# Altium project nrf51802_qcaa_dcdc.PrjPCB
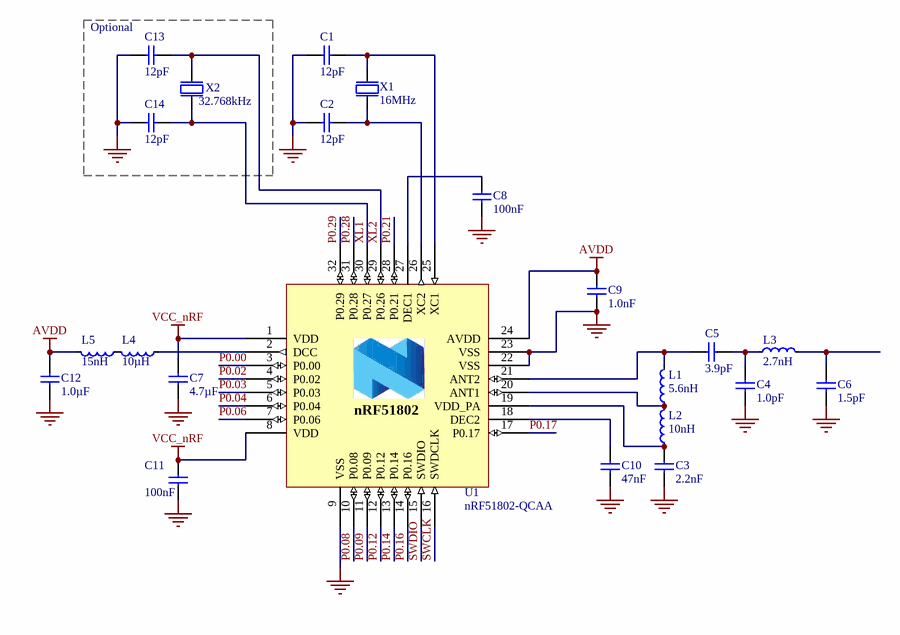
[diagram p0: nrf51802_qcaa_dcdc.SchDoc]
1 sheet, 22 parts. Net scope: global (net labels, ports and power ports of the same name join across sheets).
Board file: nrf51802_qcaa_dcdc.PcbDoc

## Sheet nrf51802_qcaa_dcdc.SchDoc: nRF51802-QCAA Reference Layout (DCDC)
size A4; Revision: 1.0; SheetNumber: 1; SheetTotal: 1; DrawnBy: RUBR; DocumentSize: A4; PCAName: nRF51802-QCAA Reference Layout (DCDC)

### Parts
C1  12pF  [CAPC1005X04L]
C2  12pF  [CAPC1005X04L]
C3  2.2nF  [CAPC1005X04L]
C4  1.0pF  [CAPC1005X04L]
C5  3.9pF  [CAPC1005X04L]
C6  1.5pF  [CAPC1005X04L]
C7  4.7µF  [CAPC1608X06L]
C8  100nF  [CAPC1005X04L]
C9  1.0nF  [CAPC1005X04L]
C10  47nF  [CAPC1005X04L]
C11  100nF  [CAPC1005X04L]
C12  1.0µF  [CAPC1608X06L]
C13  12pF  [CAPC1005X04L]
C14  12pF  [CAPC1005X04L]
L1  5.6nH  [INDC1005X04L]
L2  10nH  [INDC1005X04L]
L3  2.7nH  [INDC1005X04L]
L4  10µH  [INDC1608X06L]
L5  15nH  [INDC1005X04L]
U1  nRF51802-QCAA  [Nordic_QFN50P500X500X90-33N]
X1  16MHz  [BT-XTAL_2520]
X2  32.768kHz  [XTAL_3215]

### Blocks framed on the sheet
Optional: C13 C14 X2

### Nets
AVDD: C9.1 C12.2 L5.2 U1.24(AVDD)
GND: C1.2 C2.2 C3.2 C4.2 C6.2 C7.2 C8.2 C9.2 C10.2 C11.2 C12.1 C13.1 C14.1 U1.9(VSS) U1.22(VSS) U1.23(VSS) U1.33 X1.2(GND) X1.4(GND)
VCC_nRF: C7.1 C11.1 U1.1(VDD) U1.8(VDD)
P0.00: U1.3(P0.00)
P0.02: U1.4(P0.02)
P0.03: U1.5(P0.03)
P0.04: U1.6(P0.04)
P0.06: U1.7(P0.06)
P0.08: U1.10(P0.08)
P0.09: U1.11(P0.09)
P0.12: U1.12(P0.12)
P0.14: U1.13(P0.14)
P0.16: U1.14(P0.16)
P0.17: U1.17(P0.17)
P0.21: U1.28(P0.21)
P0.28: U1.31(P0.28)
P0.29: U1.32(P0.29)
SWCLK: U1.16(SWDCLK)
SWDIO: U1.15(SWDIO)
XL1: C14.2 U1.30(P0.27) X2.2(out)
XL2: C13.2 U1.29(P0.26) X2.1(inp)
NetC1_1: C1.1 U1.25(XC1) X1.1(inp)
NetC2_1: C2.1 U1.26(XC2) X1.3(out)
NetC3_1: C3.1 L2.1 U1.19(VDD_PA)
NetC4_1: C4.1 C5.2 L3.1
NetC5_1: C5.1 L1.2 U1.21(ANT2)
NetC6_1: C6.1 L3.2
NetC8_1: C8.1 U1.27(DEC1)
NetC10_1: C10.1 U1.18(DEC2)
NetL1_1: L1.1 L2.2 U1.20(ANT1)
NetL4_1: L4.1 U1.2(DCC)
NetL4_2: L4.2 L5.1

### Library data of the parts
C1 C2 C13 C14 = C0402-12p: Capacitor, NP0, ±2%; Note: 50V; Artikkelnr Noca: 20029159; Artikkelnr Simpro: N.A.
C3 = C0402-2n2: Capacitor, X7R, ±10%; Note: 50V; Artikkelnr Noca: 20039221; Artikkelnr Simpro: N.A.
C4 = C0402-1.0p: Capacitor, NP0, ±0.1pF; Note: 50V; Artikkelnr Noca: 20029140; Artikkelnr Simpro: N.A.
C5 = C0402-3.9p: Capacitor, NP0, ±0.1pF; Note: 50V; Artikkelnr Noca: N.A.
C6 = C0402-1.5p: Capacitor, NP0, ±0.1pF; Note: 50V; Artikkelnr Noca: 20029139; Artikkelnr Simpro: N.A.
C7 = C0603-4µ7: Capacitor, X5R, ±10%; Note: 6.3V; Artikkelnr Noca: 20069060; Artikkelnr Simpro: N.A.
C8 C11 = C0402-100n: Capacitor, X7R, ±10%; Note: 16V; Artikkelnr Noca: 20039200; Artikkelnr Simpro: N.A.
C9 = C0402-1n0: Capacitor, X7R, ±10%; Note: 50V; Artikkelnr Noca: 20039223; Artikkelnr Simpro: N.A.
C10 = C0402-47n: Capacitor, X7R, ±10%; Note: Chip Cap 10%; Artikkelnr Noca: 20039389; Artikkelnr Simpro: N.A.
C12 = C0603-1µ0: Capacitor, X7R, ±10%; Note: 16V; Artikkelnr Noca: 20039335; Artikkelnr Simpro: N.A.
L1 = L0402-5n6: High frequency chip inductor ±5%; Manufacturer: Murata; Manufacturer Part Number: LQP15MN5N6B02D; Artikkelnr Noca: 33029161; Artikkelnr Simpro: N.A.
L2 = L0402-10n: High frequency chip inductor ±5%; Manufacturer: Murata; Manufacturer Part Number: LQP15MN10NG02D; Artikkelnr Noca: 33029425; Artikkelnr Simpro: N.A.
L3 = L0402-2n7: High frequency chip inductor ±5%; Manufacturer: Murata; Manufacturer Part Number: LQP15MN2N7B02D; Artikkelnr Noca: 33029150; Artikkelnr Simpro: N.A.
L4 = L0603-10µ: Chip inductor, IDC,min = 50 mA, ±20%; Manufacturer: Taiyo Yuden; Manufacturer Part Number: LBMF1608T100K; 2nd source part number: 178-6105; Note: LBMF1608T100K 10µH 80mA 0603; Artikkelnr Noca: 33029314; Artikkelnr Simpro: N.A.
L5 = L0402-15n: High frequency chip inductor ±10%; Manufacturer: Taiyo Yuden; Manufacturer Part Number: HK100515NJ-T; 2nd source part number: 658-1328; Artikkelnr Noca: 33029323; Artikkelnr Simpro: N.A.
U1 = nRF51802-QCAA: Multi-protocol Bluetooth Low Energy and 2.4GHz proprietary system-on-chip; Manufacturer: Nordic Semiconductor; Note: nRF51802 - QFN32 5x5 0.5mm pitch; Artikkelnr Noca: N.A.
X1 = XTAL_SMD2520_16MHz_8pF_NDK: XTAL SMD 2520, 16MHz, 8pF, ±40ppm; Manufacturer: NDK; Manufacturer Part Number: NX2520SA/16MHz/EXS00A-CS06713; Note: XTAL SMD 16.000MHz; Artikkelnr Noca: 22019192; Artikkelnr Simpro: N.A.
X2 = XTAL_FC-135 32.768k: XTAL SMD 3215, 32.768kHz, 9pF, ±20ppm; Manufacturer: Epson Toyocom; Manufacturer Part Number: FC-135 32.768KHZ ±20PPM,9.0PF; 2nd source part number: 127-8037; Note: XTAL SMD 32.768kHz, 3215; Artikkelnr Noca: 22019091; Artikkelnr Simpro: N.A.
